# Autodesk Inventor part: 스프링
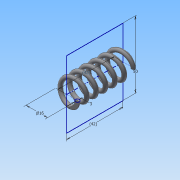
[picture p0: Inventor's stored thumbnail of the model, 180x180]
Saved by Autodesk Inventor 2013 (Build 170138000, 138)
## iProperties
Created: 2015-12
Part Number: 스프링
Material: 일반
Document SubType Name: Modeling
Designer: Administrator
Density: 1 g/cm^3
Mass: -0.0309105 g
Surface Area: 28.4714 cm^2
Volume: -0.0309105 cm^3
Author: Administrator
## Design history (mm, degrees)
sketch "스케치2"
  geometry: L1 (0, 0)-(0, 42); L2 (0, 0)-(8, 0); L3 (0, 42)-(8, 42); C1 r 1.5 at (8, 0)
  constraints: 6 end point, 1 centre point, 1 horizontal alignment, 1 parallel, 1 perpendicular, 1 vertical
  dimensions: "d0" = 42 distance of L1.start L1.end (derived); "d1" = 3 diameter of C1; "d2" = 16 diameter of L2.end L1
feature "코일1" sketch "스케치2" pitch "d3" = 10; turns "d5" = 6; dims "d4" = 41.99997 (computed from d0), "d6" = 0, angle "d7" = 90 deg, angle "d8" = 90 deg, "d9" = 0, "d10" = 0
sketch "스케치3"
  geometry: L1 (42, 25)-(0, 25); L2 (0, 25)-(0, -25); L3 (0, -25)-(42, -25); L4 (42, -25)-(42, 25); 2 further points
  constraints: 8 end point, 2 parallel, 1 coincident, 1 horizontal, 1 midpoint, 1 perpendicular
  dimensions: "d11" = 41.99997 distance of L2.end L3.end (derived); "d13" = 50 distance of L3.end L1.start
extrude "돌출1" sketch "스케치3" stored distance "d14" = 10; taper "d15" = 0 deg
node "솔리드1"
